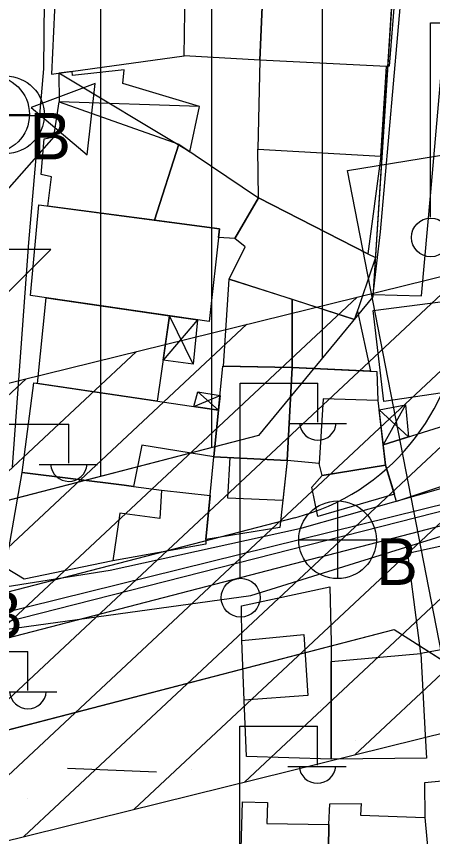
# Model space of a CAD drawing. Extents: x 417997 to 421451, y 4451742 to 4455216.
# Drawn here: x 419754.1 to 419791.7, y 4452640.4 to 4452714.3 of the extents above; entities that cross this region are included whole.
import ezdxf

# ---------------------------------------------------------------- set-up
doc = ezdxf.new("R2010")
doc.units = 0
for name, color, linetype in [('ADAKENARI', 7, 'Continuous'), ('B_Mesken', 7, 'Continuous'), ('B_Sundurma', 7, 'Continuous'), ('B_Teras', 7, 'Continuous'), ('Default', 7, 'Continuous'), ('Hat_ENH', 7, 'Continuous'), ('KALDIRIM', 7, 'Continuous'), ('PL_AYA_PARK_DINLENME', 7, 'Continuous'), ('PL_KON_MEV_350', 7, 'Continuous'), ('S_Elektrik_Diregi', 7, 'Continuous'), ('S_Rogar_Kapagi', 7, 'Continuous'), ('S_Rogar_Kapagi_Buski', 7, 'Continuous'), ('S_Trafo_acik_tip', 7, 'Continuous'), ('Sinir_Duvar_tek_tarafa_ait', 7, 'Continuous'), ('SN_KENTSEL_DONUSUM', 7, 'Continuous'), ('TA_ENH_154', 7, 'Continuous'), ('TA_ENH_KORUMA', 7, 'Continuous'), ('TA_ENH_TARAMA', 7, 'Continuous'), ('TR_ORTAYOGUNKONUT', 7, 'Continuous'), ('TR_PARKALANI', 7, 'Continuous'), ('Yol_Sose', 7, 'Continuous')]:
    doc.layers.add(name, color=color, linetype=linetype)

# ---------------------------------------------------------------- blocks, each defined once
blk = doc.blocks.new('POINT_DISPLAY')
at = {"layer": 'Default'}
blk.add_line((0, 0), (0, 0), dxfattribs=at)

msp = doc.modelspace()

# ---------------------------------------------------------------- linework, layer by layer
at = {"layer": 'ADAKENARI'}
for p, q in [((419805.412, 4452988.482), (419786.294, 4452689.029)), ((419805.412, 4452988.482), (419786.294, 4452689.029)), ((419786.294, 4452689.029), (419775.978, 4452676.538)), ((419786.294, 4452689.029), (419775.978, 4452676.538)), ((419775.978, 4452676.538), (419568.876, 4452622.815)), ((419775.978, 4452676.538), (419568.876, 4452622.815)), ((419747.044, 4452648.371), (419788.221, 4452659.052)), ((419747.044, 4452648.371), (419788.221, 4452659.052)), ((419788.221, 4452659.052), (419799.732, 4452651.732)), ((419788.221, 4452659.052), (419799.732, 4452651.732))]:
    msp.add_line(p, q, dxfattribs=at)
at = {"layer": 'B_Mesken'}
for points in [[(419757.743, 4452718.749), (419757.29, 4452709.089), (419769.263, 4452710.757), (419769.357, 4452716.722), (419771.934, 4452717.005), (419772.027, 4452718.811)], [(419772.027, 4452718.811), (419775.838, 4452718.723), (419776.458, 4452718.661), (419776.085, 4452710.36), (419769.263, 4452710.757), (419769.357, 4452716.722), (419771.934, 4452717.005)], [(419776.085, 4452710.36), (419776.458, 4452718.661), (419788.375, 4452717.701), (419787.769, 4452709.817), (419787.508, 4452709.802)], [(419776.085, 4452710.36), (419775.902, 4452702.332), (419786.993, 4452701.717), (419787.508, 4452709.802)], [(419756.978, 4452697.213), (419757.313, 4452699.841), (419756.359, 4452700.061), (419756.656, 4452703.274), (419757.507, 4452703.454), (419758.009, 4452706.594), (419768.776, 4452702.791), (419766.581, 4452695.947)], [(419768.776, 4452702.791), (419775.96, 4452697.952), (419773.846, 4452694.279), (419772.369, 4452694.382), (419772.457, 4452695.172), (419766.581, 4452695.947)], [(419775.96, 4452697.952), (419775.902, 4452702.332), (419786.993, 4452701.717), (419785.834, 4452692.902)], [(419775.96, 4452697.952), (419785.834, 4452692.902), (419786.53, 4452692.565), (419784.636, 4452687.005), (419773.334, 4452690.636), (419774.766, 4452693.545), (419773.846, 4452694.279)], [(419755.421, 4452689.152), (419756.16, 4452697.321), (419772.457, 4452695.172), (419771.52, 4452686.798)], [(419772.815, 4452682.783), (419773.334, 4452690.636), (419779.003, 4452688.815), (419778.997, 4452682.654)], [(419767.961, 4452687.319), (419766.834, 4452679.627), (419756.051, 4452681.223), (419756.809, 4452688.949)], [(419784.892, 4452687.754), (419786.082, 4452682.337), (419778.997, 4452682.654), (419779.003, 4452688.815), (419784.636, 4452687.005)], [(419787.277, 4452679.608), (419786.31, 4452687.799), (419792.373, 4452688.572), (419797.549, 4452684.005), (419796.645, 4452682.91), (419797.077, 4452682.449), (419795.103, 4452681.959), (419795.209, 4452680.772)], [(419771.942, 4452674.614), (419772.769, 4452682.784), (419778.997, 4452682.654), (419778.556, 4452674.282)], [(419786.744, 4452679.693), (419787.431, 4452673.871), (419781.72, 4452672.941), (419781.457, 4452674.006), (419778.556, 4452674.282), (419778.997, 4452682.654), (419786.659, 4452682.311)], [(419754.669, 4452673.213), (419755.714, 4452681.273), (419772.367, 4452678.807), (419771.942, 4452674.614), (419765.454, 4452675.673), (419764.701, 4452671.927), (419763.846, 4452672.058)], [(419787.216, 4452675.695), (419798.513, 4452679.227), (419799.156, 4452678.427), (419801.064, 4452674.788), (419788.434, 4452670.601), (419787.431, 4452673.871)], [(419778.556, 4452674.282), (419777.903, 4452668.233), (419771.226, 4452667.166), (419771.586, 4452670.867), (419771.942, 4452674.614)], [(419788.233, 4452671.256), (419781.32, 4452669.241), (419780.785, 4452671.873), (419781.72, 4452672.941), (419787.431, 4452673.871)], [(419767.229, 4452671.599), (419771.61, 4452671.119), (419771.226, 4452667.166), (419771.212, 4452666.749), (419762.823, 4452665.235), (419754.824, 4452663.58), (419753.146, 4452664.623), (419754.669, 4452673.213), (419763.846, 4452672.058), (419764.701, 4452671.927)], [(419789.433, 4452665.929), (419796.717, 4452667.511), (419797.446, 4452658.111), (419790.599, 4452656.888), (419790.303, 4452659.187)], [(419774.454, 4452661.171), (419782.414, 4452662.91), (419782.518, 4452657.921), (419782.533, 4452647.364), (419774.889, 4452647.61), (419774.693, 4452652.687), (419774.46, 4452658.058)], [(419782.521, 4452656.177), (419790.599, 4452656.888), (419791.012, 4452649.514), (419791.128, 4452647.445), (419782.533, 4452647.364)]]:
    msp.add_lwpolyline(points, close=True, dxfattribs=at)
at = {"layer": 'B_Sundurma'}
for p, q in [((419769.786, 4452702.111), (419757.978, 4452709.185)), ((419770.656, 4452706.198), (419758.009, 4452706.594)), ((419770.471, 4452686.952), (419767.377, 4452683.336)), ((419770.095, 4452682.978), (419767.961, 4452687.319)), ((419770.508, 4452680.467), (419772.367, 4452678.807)), ((419770.142, 4452679.137), (419772.503, 4452680.152)), ((419786.843, 4452678.85), (419789.508, 4452676.412)), ((419789.226, 4452679.309), (419787.216, 4452675.695))]:
    msp.add_line(p, q, dxfattribs=at)
for points in [[(419769.786, 4452702.111), (419770.656, 4452706.198), (419763.749, 4452708.25), (419763.867, 4452709.496), (419759.184, 4452708.983), (419759.162, 4452709.35), (419757.978, 4452709.185), (419758.009, 4452706.594), (419768.776, 4452702.791)], [(419770.471, 4452686.952), (419770.095, 4452682.978), (419767.377, 4452683.336), (419767.961, 4452687.319)], [(419770.142, 4452679.137), (419770.508, 4452680.467), (419772.503, 4452680.152), (419772.367, 4452678.807)], [(419786.843, 4452678.85), (419789.226, 4452679.309), (419789.508, 4452676.412), (419787.216, 4452675.695)]]:
    msp.add_lwpolyline(points, close=True, dxfattribs=at)
at = {"layer": 'B_Teras'}
for points in [[(419778.997, 4452682.654), (419786.659, 4452682.311), (419786.744, 4452679.693), (419781.809, 4452679.854), (419781.457, 4452674.006), (419778.556, 4452674.282)], [(419778.167, 4452670.682), (419773.209, 4452670.887), (419773.432, 4452674.539), (419778.556, 4452674.282)], [(419767.229, 4452671.599), (419767.078, 4452669.048), (419763.457, 4452669.533), (419762.823, 4452665.235), (419754.824, 4452663.58), (419753.146, 4452664.623), (419754.669, 4452673.213), (419763.846, 4452672.058), (419764.701, 4452671.927)], [(419774.693, 4452652.687), (419774.46, 4452658.058), (419780.053, 4452658.604), (419780.43, 4452653.114)], [(419791.669, 4452634.617), (419799.903, 4452635.658), (419798.565, 4452644.28), (419793.373, 4452643.843), (419793.174, 4452645.436), (419790.947, 4452645.232), (419790.976, 4452642.094)], [(419774.52, 4452643.518), (419776.787, 4452643.465), (419776.731, 4452641.57), (419782.33, 4452641.49), (419782.241, 4452634.883), (419774.283, 4452635.147)], [(419782.33, 4452641.49), (419782.404, 4452643.332), (419785.238, 4452643.377), (419785.176, 4452642.305), (419790.976, 4452642.094), (419791.669, 4452634.617), (419782.241, 4452634.883)]]:
    msp.add_lwpolyline(points, close=True, dxfattribs=at)
at = {"layer": 'Hat_ENH'}
msp.add_lwpolyline([(419683.155, 4452641.934), (419957.335, 4452711.677)], dxfattribs=at)
at = {"layer": 'KALDIRIM'}
for p, q in [((419779.257, 4452669.124), (419702.215, 4452649.139)), ((419779.257, 4452669.124), (419702.215, 4452649.139)), ((419781.498, 4452665.573), (419793.817, 4452668.769)), ((419781.498, 4452665.573), (419793.817, 4452668.769)), ((419781.498, 4452665.573), (419703.347, 4452645.3)), ((419781.498, 4452665.573), (419703.347, 4452645.3))]:
    msp.add_line(p, q, dxfattribs=at)
msp.add_arc((419774.235, 4452688.483), 20, 284.5422, 356.34714, dxfattribs=at)
msp.add_arc((419774.235, 4452688.483), 20, 284.5422, 356.34714, dxfattribs=at)
at = {"layer": 'PL_AYA_PARK_DINLENME'}
msp.add_lwpolyline([(419788.221, 4452659.052), (419799.732, 4452651.732), (419803.365, 4452632.236), (419747.044, 4452635.415), (419747.044, 4452648.371)], close=True, dxfattribs=at)
msp.add_lwpolyline([(419788.221, 4452659.052), (419799.732, 4452651.732), (419803.365, 4452632.236), (419747.044, 4452635.415), (419747.044, 4452648.371)], close=True, dxfattribs=at)
at = {"layer": 'PL_KON_MEV_350'}
msp.add_lwpolyline([(419796.331, 4452996.105), (419805.412, 4452988.482), (419786.294, 4452689.029), (419775.978, 4452676.538), (419568.876, 4452622.815), (419561.752, 4452629.972), (419581.871, 4452706.077), (419635.792, 4452719.454), (419637.405, 4452760.32), (419700.317, 4452851.73), (419754.087, 4452844.74), (419741.182, 4452876.464), (419703.543, 4452885.605), (419700.317, 4452851.73), (419637.405, 4452760.32), (419580.562, 4452749.662), (419577.387, 4452855.396), (419570.344, 4452931.114), (419579.136, 4452943.428)], close=True, dxfattribs=at)
at = {"layer": 'S_Elektrik_Diregi'}
for p, q in [((419791.474, 4452696.221), (419791.474, 4452713.721)), ((419791.474, 4452713.721), (419798.474, 4452713.721)), ((419774.329, 4452663.752), (419774.329, 4452681.252)), ((419774.329, 4452681.252), (419781.329, 4452681.252)), ((419781.329, 4452677.752), (419781.329, 4452681.252)), ((419751.864, 4452677.55), (419758.864, 4452677.55)), ((419758.864, 4452674.05), (419758.864, 4452677.55)), ((419778.669, 4452677.612), (419783.919, 4452677.612)), ((419756.204, 4452673.91), (419761.454, 4452673.91)), ((419748.182, 4452657.059), (419755.182, 4452657.059)), ((419755.182, 4452653.559), (419755.182, 4452657.059)), ((419752.522, 4452653.419), (419757.772, 4452653.419)), ((419774.287, 4452632.838), (419774.287, 4452650.338)), ((419774.287, 4452650.338), (419781.287, 4452650.338)), ((419781.287, 4452646.838), (419781.287, 4452650.338)), ((419778.627, 4452646.698), (419783.877, 4452646.698))]:
    msp.add_line(p, q, dxfattribs=at)
for centre in [(419791.51, 4452694.386), (419774.365, 4452661.917)]:
    msp.add_circle(centre, 1.75, dxfattribs=at)
for centre in [(419781.33, 4452677.765), (419758.865, 4452674.063), (419755.183, 4452653.572), (419781.288, 4452646.851)]:
    msp.add_arc(centre, 1.658, 184.83843, 355.14641, dxfattribs=at)
at = {"layer": 'S_Rogar_Kapagi'}
msp.add_line((419749.641, 4452705.373), (419756.641, 4452705.373), dxfattribs=at)
msp.add_circle((419753.158, 4452705.436), 3.5, dxfattribs=at)
at = {"layer": 'S_Rogar_Kapagi_Buski'}
for p, q in [((419748.312, 4452705.475), (419755.312, 4452705.475)), ((419783.102, 4452670.636), (419783.102, 4452663.636)), ((419779.602, 4452667.136), (419786.603, 4452667.136))]:
    msp.add_line(p, q, dxfattribs=at)
for centre in [(419751.812, 4452705.475), (419783.102, 4452667.136)]:
    msp.add_circle(centre, 3.5, dxfattribs=at)
at = {"layer": 'S_Trafo_acik_tip'}
msp.add_lwpolyline([(419760.514, 4452701.841), (419761.249, 4452708.246), (419755.474, 4452706.111)], close=True, dxfattribs=at)
msp.add_lwpolyline([(419747.599, 4452683.641), (419757.259, 4452693.301), (419748.544, 4452693.301), (419757.994, 4452703.976)], dxfattribs=at)
at = {"layer": 'Sinir_Duvar_tek_tarafa_ait'}
msp.add_lwpolyline([(419758.76, 4452646.562), (419766.772, 4452646.233)], dxfattribs=at)
at = {"layer": 'SN_KENTSEL_DONUSUM'}
for p, q in [((419784.011, 4452700.413), (419906.016, 4452720.508)), ((419784.011, 4452700.413), (419906.016, 4452720.508)), ((419824.919, 4452490.134), (419784.011, 4452700.413)), ((419824.919, 4452490.134), (419784.011, 4452700.413))]:
    msp.add_line(p, q, dxfattribs=at)
at = {"layer": 'TA_ENH_154'}
msp.add_lwpolyline([(421244.229, 4452871.733), (420603.453, 4452866.932), (420104.111, 4452747.147), (419709.07, 4452649.72), (419353.297, 4452559.565), (419284.532, 4452601.288), (419287.681, 4452599.871), (419484.079, 4452691.722), (419833.947, 4454863.938), (419862.826, 4455014.236)], dxfattribs=at)
msp.add_lwpolyline([(421244.229, 4452871.733), (420603.453, 4452866.932), (420104.111, 4452747.147), (419709.07, 4452649.72), (419353.297, 4452559.565), (419284.532, 4452601.288), (419287.681, 4452599.871), (419484.079, 4452691.722), (419833.947, 4454863.938), (419862.826, 4455014.236)], dxfattribs=at)
at = {"layer": 'TA_ENH_KORUMA'}
msp.add_lwpolyline([(419883.153, 4455014.021), (419853.647, 4454860.459), (419502.143, 4452678.088), (419329.549, 4452597.37), (419356.508, 4452581.013), (419704.218, 4452669.124), (420099.383, 4452766.582), (420601.013, 4452886.916), (421244.438, 4452891.737)], dxfattribs=at)
msp.add_lwpolyline([(419883.153, 4455014.021), (419853.647, 4454860.459), (419502.143, 4452678.088), (419329.549, 4452597.37), (419356.508, 4452581.013), (419704.218, 4452669.124), (420099.383, 4452766.582), (420601.013, 4452886.916), (421244.438, 4452891.737)], dxfattribs=at)
at = {"layer": 'TA_ENH_TARAMA'}
for p, q in [((419713.921, 4452630.315), (420108.839, 4452727.712)), ((419713.921, 4452630.315), (420108.839, 4452727.712)), ((419784.66, 4452647.761), (419844.552, 4452703.734)), ((419784.66, 4452647.761), (419844.552, 4452703.734)), ((419774.711, 4452645.307), (419834.603, 4452701.281)), ((419774.711, 4452645.307), (419834.603, 4452701.281)), ((419764.763, 4452642.854), (419824.655, 4452698.827)), ((419764.763, 4452642.854), (419824.655, 4452698.827)), ((419754.814, 4452640.4), (419814.706, 4452696.374)), ((419754.814, 4452640.4), (419814.706, 4452696.374)), ((419744.865, 4452637.946), (419804.757, 4452693.92)), ((419744.865, 4452637.946), (419804.757, 4452693.92)), ((419734.916, 4452635.493), (419794.808, 4452691.466)), ((419734.916, 4452635.493), (419794.808, 4452691.466)), ((419724.967, 4452633.039), (419784.859, 4452689.013)), ((419724.967, 4452633.039), (419784.859, 4452689.013)), ((419715.018, 4452630.585), (419774.91, 4452686.559)), ((419715.018, 4452630.585), (419774.91, 4452686.559)), ((419704.981, 4452628.049), (419764.961, 4452684.105)), ((419704.981, 4452628.049), (419764.961, 4452684.105)), ((419694.933, 4452625.503), (419755.012, 4452681.652)), ((419694.933, 4452625.503), (419755.012, 4452681.652))]:
    msp.add_line(p, q, dxfattribs=at)
at = {"layer": 'TR_ORTAYOGUNKONUT'}
for p, q in [((419781.752, 4452683.529), (419781.752, 4452992.569)), ((419781.752, 4452683.529), (419781.752, 4452992.569)), ((419771.752, 4452675.442), (419771.752, 4452990.144)), ((419771.752, 4452675.442), (419771.752, 4452990.144)), ((419761.752, 4452672.848), (419761.752, 4452987.719)), ((419761.752, 4452672.848), (419761.752, 4452987.719))]:
    msp.add_line(p, q, dxfattribs=at)
at = {"layer": 'Yol_Sose'}
for points in [[(419753.782, 4452673.72), (419755.264, 4452693.941), (419756.612, 4452709.569), (419756.731, 4452721.886), (419757.261, 4452737.798), (419757.036, 4452748.484), (419756.934, 4452751.846), (419756.957, 4452752.064), (419757.055, 4452752.21)], [(419788.903, 4452717.138), (419786.934, 4452694.903), (419786.294, 4452689.253), (419790.671, 4452689.13), (419791.523, 4452698.455), (419793.097, 4452716.715)], [(419751.321, 4452658.811), (419775.275, 4452662.115), (419792.528, 4452667.495), (419808.819, 4452672.39), (419828.568, 4452677.474), (419845.17, 4452681.202), (419859.663, 4452683.403), (419860.079, 4452683.198), (419860.366, 4452682.828), (419860.468, 4452682.018), (419859.11, 4452674.998), (419855.761, 4452659.442), (419845.728, 4452639.909), (419845.562, 4452639.833), (419844.827, 4452639.55), (419830.863, 4452638.733), (419816.805, 4452636.902), (419791.652, 4452634.275), (419766.859, 4452635.64)], [(419824.058, 4452682.808), (419800.867, 4452674.129), (419779.67, 4452668.138), (419762.603, 4452664.368)], [(419762.603, 4452664.368), (419753.312, 4452662.902)]]:
    msp.add_lwpolyline(points, dxfattribs=at)

# ---------------------------------------------------------------- block references
at = {"layer": 'TR_PARKALANI', "xscale": 0.1, "yscale": 0.10000000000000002}
for p in [(419781.589, 4452652.026), (419781.589, 4452652.026), (419784.7, 4452649.03), (419784.7, 4452649.03), (419769.928, 4452646.425), (419769.928, 4452646.425), (419755.156, 4452643.82), (419755.156, 4452643.82)]:
    msp.add_blockref('POINT_DISPLAY', p, dxfattribs=at)

# ---------------------------------------------------------------- texts
at = {"layer": 'S_Rogar_Kapagi_Buski'}
for p in [(419755.312, 4452701.41), (419786.603, 4452663.071), (419750.972, 4452658.281)]:
    msp.add_text('B', height=4.2, dxfattribs=at).set_placement(p)

doc.saveas('drawing.dxf')
